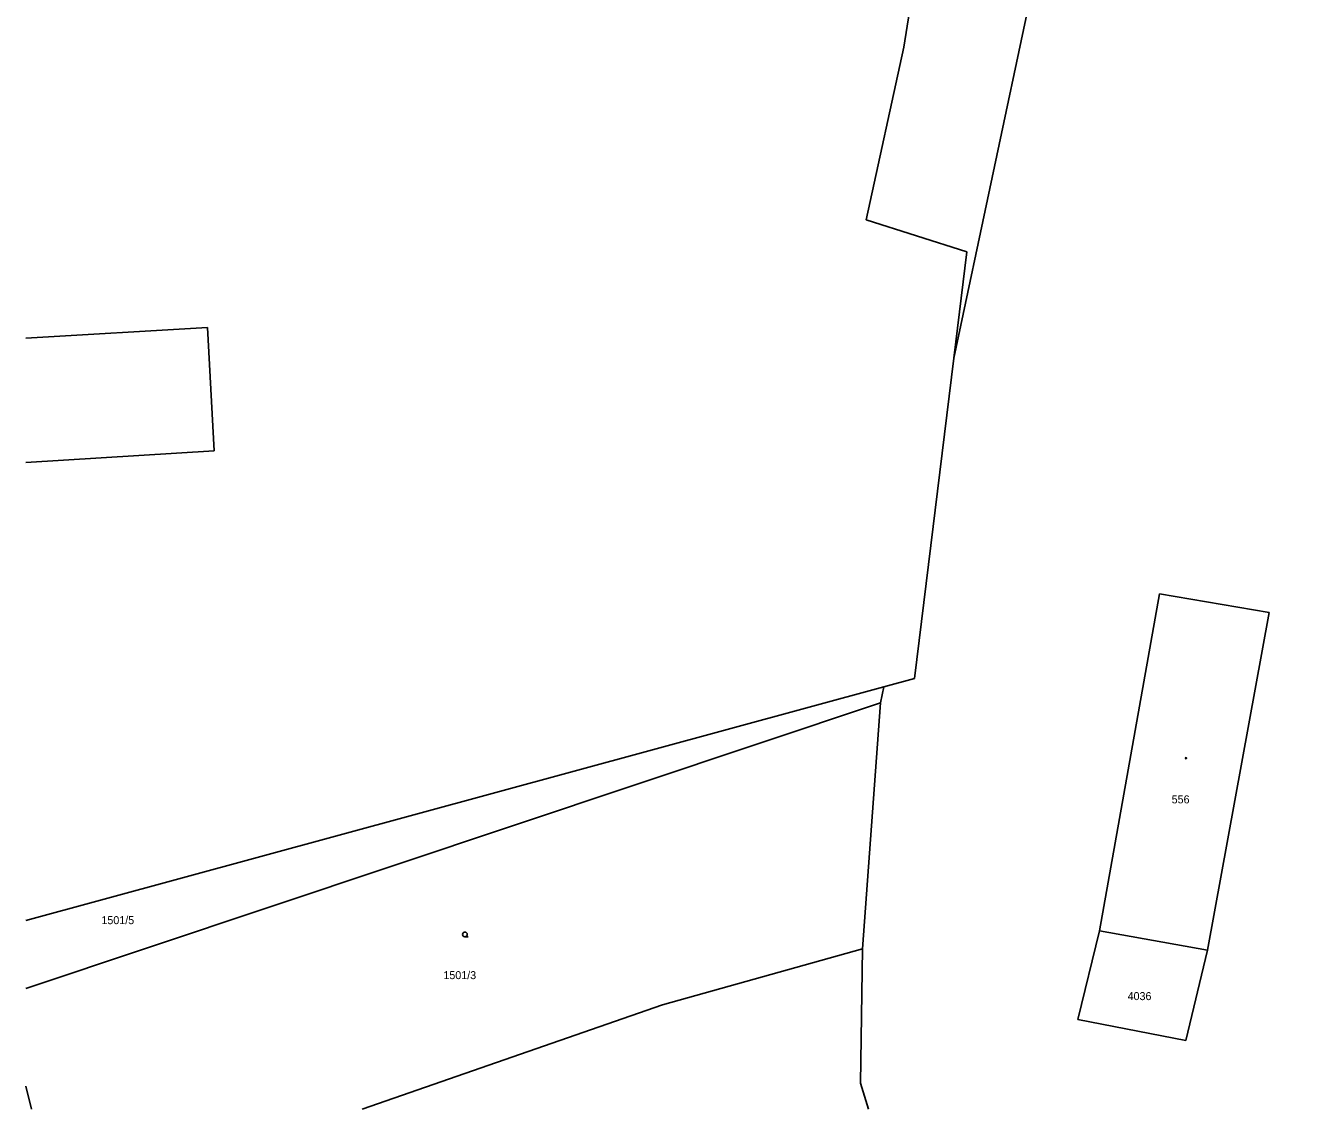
# Model space of a CAD drawing. Extents: x -866624 to -866276, y -1050208 to -1049940.
# Drawn here: x -866623.7 to -866543.1, y -1050208.1 to -1050140.5 of the extents above; entities that cross this region are included whole.
import ezdxf

# ---------------------------------------------------------------- set-up
doc = ezdxf.new("R2010")
doc.units = 0
for name, color, linetype in [('Default', 7, 'Continuous'), ('Hranice', 7, 'Continuous'), ('Hranice-budov', 7, 'Continuous'), ('Parcela-pozemkova', 7, 'Continuous'), ('Parcela-stavebni', 7, 'Continuous'), ('znacky-budov', 7, 'Continuous'), ('Znacky-kultury', 7, 'Continuous')]:
    doc.layers.add(name, color=color, linetype=linetype)

# ---------------------------------------------------------------- blocks, each defined once
blk = doc.blocks.new('p_zahr')
at = {"layer": 'Default'}
blk.add_line((0, -0.75), (0.99, -0.75), dxfattribs=at)
blk.add_circle((0, 0), 0.75, dxfattribs=at)
blk = doc.blocks.new('s_zdena')
at = {"layer": 'Default'}
blk.add_circle((0, 0), 0.175, dxfattribs=at)
for start, end in [(0, 180), (180, 0)]:
    blk.add_arc((0, 0), 0.0875, start, end, dxfattribs=at)

msp = doc.modelspace()

# ---------------------------------------------------------------- linework, layer by layer
at = {"layer": 'Hranice'}
for p, q in [((-866565.77, -1050161.24), (-866543.07, -1050054.21)), ((-866568.88, -1050141.81), (-866567.75, -1050134.64)), ((-866571.23, -1050152.59), (-866568.88, -1050141.81)), ((-866564.96, -1050154.6), (-866571.23, -1050152.59)), ((-866565.77, -1050161.24), (-866564.96, -1050154.6)), ((-866623.725, -1050159.991), (-866612.38, -1050159.31)), ((-866612.38, -1050159.31), (-866611.97, -1050167.02)), ((-866568.23, -1050181.25), (-866565.77, -1050161.24)), ((-866611.97, -1050167.02), (-866623.725, -1050167.746)), ((-866552.91, -1050175.95), (-866556.66, -1050197.01)), ((-866546.07, -1050177.11), (-866552.91, -1050175.95)), ((-866549.91, -1050198.22), (-866546.07, -1050177.11)), ((-866568.23, -1050181.25), (-866570.13, -1050181.77)), ((-866570.13, -1050181.77), (-866623.725, -1050196.365)), ((-866570.34, -1050182.77), (-866570.13, -1050181.77)), ((-866570.34, -1050182.77), (-866623.725, -1050200.604)), ((-866570.34, -1050182.77), (-866571.46, -1050198.12)), ((-866556.66, -1050197.01), (-866558.02, -1050202.54)), ((-866549.91, -1050198.22), (-866556.66, -1050197.01)), ((-866583.95, -1050201.63), (-866571.46, -1050198.12)), ((-866571.46, -1050198.12), (-866571.6, -1050206.52)), ((-866551.27, -1050203.85), (-866549.91, -1050198.22)), ((-866602.724, -1050208.146), (-866583.95, -1050201.63)), ((-866558.02, -1050202.54), (-866551.27, -1050203.85)), ((-866623.378, -1050208.146), (-866623.725, -1050206.709)), ((-866571.6, -1050206.52), (-866571.083, -1050208.146))]:
    msp.add_line(p, q, dxfattribs=at)
at = {"layer": 'Hranice-budov'}
for p, q in [((-866552.91, -1050175.95), (-866556.66, -1050197.01)), ((-866546.07, -1050177.11), (-866552.91, -1050175.95)), ((-866549.91, -1050198.22), (-866546.07, -1050177.11)), ((-866549.91, -1050198.22), (-866556.66, -1050197.01))]:
    msp.add_line(p, q, dxfattribs=at)

# ---------------------------------------------------------------- block references
at = {"layer": 'znacky-budov', "xscale": 0.2, "yscale": 0.20000000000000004}
msp.add_blockref('s_zdena', (-866551.26, -1050186.22), dxfattribs=at)
at = {"layer": 'Znacky-kultury', "xscale": 0.2, "yscale": 0.20000000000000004}
msp.add_blockref('p_zahr', (-866596.3, -1050197.23), dxfattribs=at)

# ---------------------------------------------------------------- texts
at = {"layer": 'Parcela-pozemkova'}
for s, p in [('1501/5', (-866619.004, -1050196.589)), ('1501/3', (-866597.644, -1050200.023)), ('4036', (-866554.909, -1050201.333))]:
    msp.add_text(s, height=0.5, dxfattribs=at).set_placement(p)
at = {"layer": 'Parcela-stavebni'}
msp.add_text('556', height=0.5, dxfattribs=at).set_placement((-866552.157, -1050189.043))

doc.saveas('drawing.dxf')
